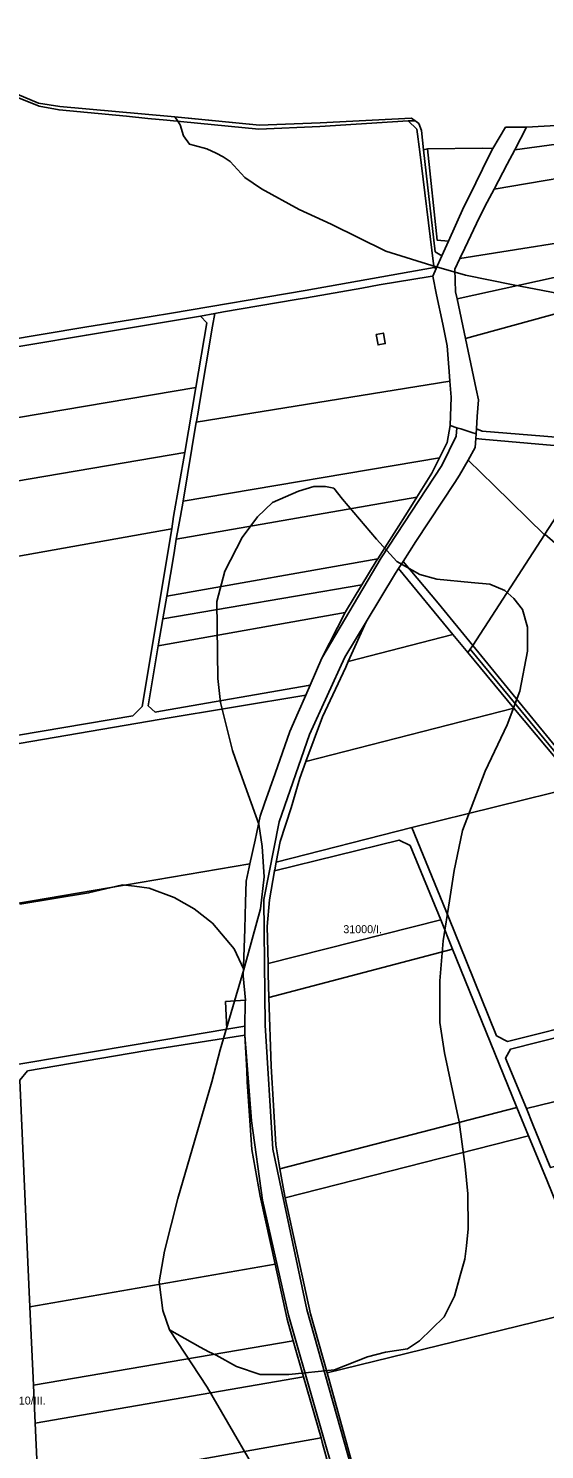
# Model space of a CAD drawing. Extents: x -541351 to -537540, y -1162694 to -1159725.
# Drawn here: x -539786 to -539463, y -1160828 to -1159940 of the extents above; entities that cross this region are included whole.
import ezdxf

# ---------------------------------------------------------------- set-up
doc = ezdxf.new("R2010")
doc.units = 0
for name, color, linetype in [('95560013', 7, 'Continuous'), ('95600013', 7, 'Continuous'), ('95610013', 7, 'Continuous'), ('95640013', 7, 'Continuous'), ('95660013', 7, 'Continuous')]:
    doc.layers.add(name, color=color, linetype=linetype)

msp = doc.modelspace()

# ---------------------------------------------------------------- linework, layer by layer
at = {"layer": '95560013'}
for points in [[(-539308.49, -1159974.08), (-539354.55, -1159990.5), (-539425.35, -1160007.86), (-539482.04, -1160015.57), (-539474.65, -1160001.49), (-539441.58, -1159999.6), (-539426.66, -1159997.49), (-539378.27, -1159985.56), (-539357.29, -1159979.97), (-539338.63, -1159973.85), (-539312.29, -1159964.05), (-539277.38, -1159950.13), (-539253.79, -1159939.77), (-539256.52, -1159952.89)], [(-539482.04, -1160015.57), (-539425.35, -1160007.86), (-539354.55, -1159990.5), (-539308.49, -1159974.08), (-539256.52, -1159952.89), (-539261.76, -1159978), (-539348.12, -1160009.46), (-539421.4, -1160027.65), (-539494.95, -1160040.2), (-539486.82, -1160024.7)], [(-539261.76, -1159978), (-539266.2, -1159999.29), (-539267.32, -1160019.26), (-539320.05, -1160041.46), (-539357.51, -1160053.36), (-539416.53, -1160067.73), (-539516.34, -1160083.61), (-539513.23, -1160077.01), (-539504.15, -1160057.74), (-539499.27, -1160048.44), (-539494.95, -1160040.2), (-539421.4, -1160027.65), (-539348.12, -1160009.46)], [(-539502.2, -1160014.56), (-539495.67, -1160014.74), (-539497.71, -1160018.84), (-539510.76, -1160045.13), (-539513.78, -1160051.22), (-539523.43, -1160072.73), (-539530.43, -1160072.14), (-539536.54, -1160014.93)], [(-539516.34, -1160083.61), (-539416.53, -1160067.73), (-539357.51, -1160053.36), (-539320.05, -1160041.46), (-539267.32, -1160019.26), (-539267.84, -1160031.16), (-539267.74, -1160037), (-539315.38, -1160054.86), (-539352.56, -1160067.89), (-539407.25, -1160084.31), (-539518.09, -1160108.82), (-539519.03, -1160104.35), (-539519.41, -1160090.12)], [(-539347.53, -1160084.05), (-539398.26, -1160102.11), (-539512.88, -1160133.53), (-539518.09, -1160108.82), (-539407.25, -1160084.31), (-539352.56, -1160067.89), (-539315.38, -1160054.86), (-539267.74, -1160037), (-539267.44, -1160054.36)], [(-539512.88, -1160133.53), (-539398.26, -1160102.11), (-539347.53, -1160084.05), (-539267.44, -1160054.36), (-539250.94, -1160160.23), (-539385.29, -1160241.92), (-539422.88, -1160197.87), (-539502.48, -1160191.42), (-539505.96, -1160190.04), (-539505.45, -1160182.31), (-539504.78, -1160171.93), (-539506.16, -1160165.16)], [(-539861.7, -1160150.32), (-539749.73, -1160131.42), (-539678.3, -1160119.6), (-539674.35, -1160123.79), (-539681.25, -1160164.2), (-539874.79, -1160196.79), (-539867.81, -1160155.49)], [(-539521.72, -1160170.16), (-539522.29, -1160187.99), (-539524.21, -1160198.49), (-539528.99, -1160208.07), (-539689.24, -1160235.28), (-539681.12, -1160185.89), (-539522.63, -1160160.16)], [(-539874.79, -1160196.79), (-539681.25, -1160164.2), (-539688.29, -1160204.74), (-539881.63, -1160237.63)], [(-539463.53, -1160256.34), (-539494.99, -1160225.44), (-539511.16, -1160209.5), (-539506.72, -1160201.77), (-539506.35, -1160196.13), (-539502.7, -1160196.39), (-539428.87, -1160202.88), (-539463.26, -1160255.92)], [(-539695.22, -1160244.7), (-539696.27, -1160252.43), (-539890.14, -1160287.05), (-539882.34, -1160242.43), (-539881.63, -1160237.63), (-539688.29, -1160204.74)], [(-539528.99, -1160208.07), (-539533.82, -1160217.78), (-539543.16, -1160232.76), (-539693.55, -1160258.99), (-539690.99, -1160244.62), (-539689.24, -1160235.28)], [(-539548.99, -1160242.09), (-539555.83, -1160252.97), (-539567.65, -1160271.23), (-539699.48, -1160294.6), (-539694.9, -1160267.58), (-539693.55, -1160258.99), (-539543.16, -1160232.76)], [(-539905.29, -1160399.99), (-539909.12, -1160395.76), (-539896.76, -1160325.74), (-539890.14, -1160287.05), (-539696.27, -1160252.43), (-539714.91, -1160363.54), (-539720.67, -1160369.29), (-539807.19, -1160383.95)], [(-539567.65, -1160271.23), (-539568.53, -1160272.74), (-539577.57, -1160287.59), (-539701.9, -1160308.8), (-539699.48, -1160294.6)], [(-539586.08, -1160335.4), (-539574.91, -1160310.55), (-539556.49, -1160280.21), (-539554.76, -1160277.35), (-539520.69, -1160318.51)], [(-539587.98, -1160304.74), (-539704.76, -1160325.55), (-539701.9, -1160308.8), (-539577.57, -1160287.59), (-539587.82, -1160304.43)], [(-539711.05, -1160363.13), (-539704.76, -1160325.55), (-539587.98, -1160304.74), (-539602.6, -1160333.33), (-539609.97, -1160350.24), (-539703.31, -1160366.41), (-539706.71, -1160366.98)], [(-539602.14, -1160370.05), (-539587.64, -1160338.97), (-539586.08, -1160335.4), (-539520.69, -1160318.51), (-539511.37, -1160329.79), (-539482.59, -1160364.66), (-539612.5, -1160397.88)], [(-539622.59, -1160379.21), (-539631.8, -1160405.4), (-539638.38, -1160424.12), (-539641.15, -1160432), (-539644.34, -1160446.97), (-539647.54, -1160461.93), (-539784.61, -1160485.12), (-539921.72, -1160508.25), (-539926.62, -1160497.29), (-539911.84, -1160410.99), (-539905.99, -1160405.21), (-539806.59, -1160389.16), (-539702.88, -1160371.48), (-539612.64, -1160356.38), (-539617.44, -1160367.38)], [(-539441.86, -1160413.3), (-539546.4, -1160439.25), (-539631.19, -1160460.88), (-539628.67, -1160447.82), (-539621.83, -1160426.91), (-539616.32, -1160408.3), (-539612.5, -1160397.88), (-539482.59, -1160364.66)], [(-539546.4, -1160439.25), (-539441.86, -1160413.3), (-539435.54, -1160421.37), (-539418.31, -1160436.62), (-539347.78, -1160481.25), (-539330.09, -1160492.45), (-539328.62, -1160499.34), (-539351.71, -1160533.5), (-539356, -1160539.85), (-539433.55, -1160559.47), (-539486.63, -1160572.87), (-539493.35, -1160569.31), (-539512.18, -1160522.86), (-539523.19, -1160495.68)], [(-539636.18, -1160524.12), (-539636.65, -1160500.97), (-539635.21, -1160484.43), (-539632.14, -1160466.29), (-539554.27, -1160447.02), (-539547.47, -1160450.3), (-539528.32, -1160496.8)], [(-539650.35, -1160547.02), (-539662.68, -1160547.97), (-539661.99, -1160565.14), (-539713.66, -1160573.83), (-539798.17, -1160588.09), (-539919.97, -1160607.67), (-539919.25, -1160512.88), (-539921.72, -1160508.25), (-539784.61, -1160485.12), (-539647.54, -1160461.93), (-539647.95, -1160463.89), (-539649.83, -1160472.69), (-539650.25, -1160485.84), (-539650.77, -1160502.39), (-539651.71, -1160531.92)], [(-539636.18, -1160530.77), (-539636.18, -1160524.12), (-539528.32, -1160496.8), (-539520.92, -1160515.12), (-539635.66, -1160545.36)], [(-539635.66, -1160545.36), (-539520.92, -1160515.12), (-539494.62, -1160579.82), (-539480.65, -1160614.14), (-539628.8, -1160652.38), (-539631.37, -1160637.5), (-539634.2, -1160588.33)], [(-539661.99, -1160565.14), (-539662.68, -1160547.97), (-539650.35, -1160547.02), (-539650.41, -1160548.28), (-539650.6, -1160563.3)], [(-539474.71, -1160614.69), (-539487.77, -1160583.34), (-539484.64, -1160577.59), (-539432.01, -1160564.25), (-539361.14, -1160546.51), (-539353.04, -1160549.08), (-539330.05, -1160579.53)], [(-539646.24, -1160640.35), (-539641.09, -1160669.51), (-539631.78, -1160712.13), (-539785.07, -1160738.8), (-539786.27, -1160710.83), (-539791.3, -1160596.99), (-539786.42, -1160591.13), (-539713.08, -1160578.81), (-539650.68, -1160568.9), (-539649.42, -1160590.92), (-539649.14, -1160598.17)], [(-539307.63, -1160614.15), (-539459.78, -1160651.69), (-539460.16, -1160650.71), (-539470.7, -1160624.83), (-539474.71, -1160614.69), (-539330.05, -1160579.53), (-539328.91, -1160581.29), (-539323.61, -1160589.17)], [(-539625.46, -1160670.68), (-539626.36, -1160666.27), (-539628.8, -1160652.38), (-539480.65, -1160614.14), (-539473.34, -1160631.89)], [(-539599.23, -1160779.87), (-539609.66, -1160743.12), (-539625.46, -1160670.68), (-539473.34, -1160631.89), (-539461.68, -1160659.92), (-539430.38, -1160737.54), (-539429.99, -1160738.47)], [(-539631.78, -1160712.13), (-539624.15, -1160746.4), (-539620.46, -1160759.86), (-539782.71, -1160787.7), (-539785.07, -1160738.8)], [(-539571.49, -1160879.49), (-539576.96, -1160860.94), (-539589.32, -1160816.2), (-539599.23, -1160779.87), (-539429.99, -1160738.47), (-539398.34, -1160816), (-539391.52, -1160833.04)], [(-539613.99, -1160782.56), (-539781.7, -1160811.46), (-539782.12, -1160801.98), (-539782.71, -1160787.7), (-539620.46, -1160759.86)], [(-539779.88, -1160852.13), (-539781.7, -1160811.46), (-539613.99, -1160782.56), (-539603.06, -1160820.51)], [(-539779.88, -1160852.13), (-539603.06, -1160820.51), (-539602.29, -1160823.36), (-539590.37, -1160867.23), (-539585.53, -1160883.06), (-539772.26, -1160915.27), (-539777.27, -1160910.84)]]:
    msp.add_lwpolyline(points, close=True, dxfattribs=at)
for points in [[(-539807.19, -1160383.95), (-539720.67, -1160369.29), (-539714.91, -1160363.54), (-539696.27, -1160252.43), (-539695.22, -1160244.7), (-539688.29, -1160204.74), (-539681.25, -1160164.2), (-539674.35, -1160123.79), (-539678.3, -1160119.6), (-539669.5, -1160118.03), (-539670.89, -1160125.91), (-539678.95, -1160174.24), (-539679.95, -1160179.6), (-539680.94, -1160185.37), (-539681.12, -1160185.89), (-539689.24, -1160235.28), (-539690.99, -1160244.62), (-539693.55, -1160258.99), (-539694.9, -1160267.58), (-539699.48, -1160294.6), (-539701.9, -1160308.8), (-539704.76, -1160325.55), (-539711.05, -1160363.13), (-539706.71, -1160366.98), (-539703.31, -1160366.41), (-539609.97, -1160350.24), (-539612.64, -1160356.38), (-539702.88, -1160371.48), (-539806.59, -1160389.16)], [(-539428.87, -1160202.88), (-539502.7, -1160196.39), (-539506.35, -1160196.13), (-539506.17, -1160193.22), (-539505.96, -1160190.04), (-539502.48, -1160191.42), (-539422.88, -1160197.87)], [(-539461.68, -1160659.92), (-539473.34, -1160631.89), (-539480.65, -1160614.14), (-539494.62, -1160579.82), (-539520.92, -1160515.12), (-539528.32, -1160496.8), (-539547.47, -1160450.3), (-539554.27, -1160447.02), (-539632.14, -1160466.29), (-539632.01, -1160465.71), (-539631.19, -1160460.88), (-539546.4, -1160439.25), (-539523.19, -1160495.68), (-539512.18, -1160522.86), (-539493.35, -1160569.31), (-539486.63, -1160572.87), (-539433.55, -1160559.47)], [(-539432.01, -1160564.25), (-539484.64, -1160577.59), (-539487.77, -1160583.34), (-539474.71, -1160614.69), (-539470.7, -1160624.83), (-539460.16, -1160650.71)]]:
    msp.add_lwpolyline(points, dxfattribs=at)
at = {"layer": '95600013'}
for points in [[(-539681.12, -1160185.89), (-539680.94, -1160185.37), (-539679.95, -1160179.6), (-539678.95, -1160174.24), (-539670.89, -1160125.91), (-539669.5, -1160118.03), (-539664, -1160116.8), (-539618.67, -1160109.28), (-539612.07, -1160108.19), (-539577.54, -1160102), (-539566.81, -1160100.08), (-539534.95, -1160094.86), (-539533.26, -1160094.63), (-539530.85, -1160106.21), (-539527.02, -1160124.61), (-539524.2, -1160138.12), (-539523.4, -1160148.87), (-539523.04, -1160154.15), (-539522.63, -1160160.16)], [(-539567.41, -1160137.56), (-539562.94, -1160136.68), (-539564.1, -1160130.19), (-539568.58, -1160131.08)]]:
    msp.add_lwpolyline(points, close=True, dxfattribs=at)
at = {"layer": '95610013'}
for points in [[(-539463.53, -1160256.34), (-539508.32, -1160325.42), (-539529.95, -1160299.04), (-539551.86, -1160272.91), (-539543.76, -1160260.52), (-539519.57, -1160223.53), (-539516.64, -1160219.04), (-539511.16, -1160209.5), (-539494.99, -1160225.44)], [(-539338.32, -1160364.79), (-539393.71, -1160438.45), (-539395.56, -1160440.92), (-539397.21, -1160443.12), (-539416.61, -1160431.81), (-539432.78, -1160417.52), (-539479.17, -1160360.89), (-539508.32, -1160325.42), (-539463.53, -1160256.34), (-539463.26, -1160255.92)]]:
    msp.add_lwpolyline(points, close=True, dxfattribs=at)
at = {"layer": '95640013'}
for points in [[(-539798.34, -1159980.7), (-539779.23, -1159988.26), (-539766.75, -1159990.7), (-539724.64, -1159994.55), (-539711.31, -1159995.96), (-539699.4, -1159997.18), (-539641.86, -1160002.73), (-539603.82, -1160001.07), (-539558.33, -1159998.22), (-539548.59, -1159997.61), (-539543.22, -1160002.75), (-539541.38, -1160016.88), (-539532.72, -1160086.9), (-539532.31, -1160089.25), (-539613.04, -1160103.64), (-539696.46, -1160117.7), (-539709.27, -1160119.9), (-539750.65, -1160126.47), (-539852.54, -1160143.49)], [(-539796.96, -1159979.23), (-539779.53, -1159986.52), (-539766.36, -1159988.66), (-539696.71, -1159994.91), (-539641.55, -1160000.23), (-539603.54, -1159998.8), (-539558.79, -1159996.56), (-539546.53, -1159995.95), (-539544.3, -1159997.55), (-539548.59, -1159997.61), (-539558.33, -1159998.22), (-539603.82, -1160001.07), (-539641.86, -1160002.73), (-539699.4, -1159997.18), (-539711.31, -1159995.96), (-539724.64, -1159994.55), (-539766.75, -1159990.7), (-539779.23, -1159988.26), (-539798.34, -1159980.7)], [(-539590.55, -1160859.01), (-539623.5, -1160743.95), (-539639.73, -1160672.1), (-539646.54, -1160622.42), (-539650.68, -1160568.9), (-539650.6, -1160563.3), (-539650.41, -1160548.28), (-539650.35, -1160547.02), (-539651.71, -1160531.92), (-539650.77, -1160502.39), (-539650.25, -1160485.84), (-539649.83, -1160472.69), (-539647.95, -1160463.89), (-539647.54, -1160461.93), (-539644.34, -1160446.97), (-539641.15, -1160432), (-539638.38, -1160424.12), (-539631.8, -1160405.4), (-539622.59, -1160379.21), (-539617.44, -1160367.38), (-539612.64, -1160356.38), (-539609.97, -1160350.24), (-539602.6, -1160333.33), (-539565.42, -1160270.64), (-539527.56, -1160212.97), (-539518.65, -1160194.69), (-539518.26, -1160189.3), (-539515.77, -1160190.1), (-539508.91, -1160192.33), (-539506.17, -1160193.22), (-539506.35, -1160196.13), (-539506.72, -1160201.77), (-539511.16, -1160209.5), (-539516.64, -1160219.04), (-539519.57, -1160223.53), (-539543.76, -1160260.52), (-539551.86, -1160272.91), (-539554.76, -1160277.35), (-539556.49, -1160280.21), (-539574.91, -1160310.55), (-539588.3, -1160332.61), (-539610.26, -1160381), (-539629.2, -1160435.51), (-539638.78, -1160484.23), (-539638.04, -1160562.66), (-539633.14, -1160640.18), (-539611.99, -1160740.35), (-539579.46, -1160855.53)], [(-539579.46, -1160855.53), (-539611.99, -1160740.35), (-539633.14, -1160640.18), (-539638.04, -1160562.66), (-539638.78, -1160484.23), (-539629.2, -1160435.51), (-539610.26, -1160381), (-539588.3, -1160332.61), (-539574.91, -1160310.55), (-539586.08, -1160335.4), (-539587.64, -1160338.97), (-539602.14, -1160370.05), (-539612.5, -1160397.88), (-539616.32, -1160408.3), (-539621.83, -1160426.91), (-539628.67, -1160447.82), (-539631.19, -1160460.88), (-539632.01, -1160465.71), (-539632.14, -1160466.29), (-539635.21, -1160484.43), (-539636.65, -1160500.97), (-539636.18, -1160524.12), (-539636.18, -1160530.77), (-539635.66, -1160545.36), (-539634.2, -1160588.33), (-539631.37, -1160637.5), (-539628.8, -1160652.38), (-539626.36, -1160666.27), (-539625.46, -1160670.68), (-539609.66, -1160743.12), (-539599.23, -1160779.87), (-539589.32, -1160816.2), (-539576.96, -1160860.94)], [(-539441.86, -1160413.3), (-539482.59, -1160364.66), (-539511.37, -1160329.79), (-539509.85, -1160327.61), (-539481.11, -1160362.43), (-539434.58, -1160419.19)], [(-539434.58, -1160419.19), (-539481.11, -1160362.43), (-539509.85, -1160327.61), (-539508.32, -1160325.42), (-539479.17, -1160360.89), (-539432.78, -1160417.52)], [(-539798.17, -1160588.09), (-539713.66, -1160573.83), (-539661.99, -1160565.14), (-539650.6, -1160563.3), (-539650.68, -1160568.9), (-539713.08, -1160578.81), (-539786.42, -1160591.13)], [(-539590.37, -1160867.23), (-539602.29, -1160823.36), (-539603.06, -1160820.51), (-539613.99, -1160782.56), (-539620.46, -1160759.86), (-539624.15, -1160746.4), (-539631.78, -1160712.13), (-539641.09, -1160669.51), (-539646.24, -1160640.35), (-539649.14, -1160598.17), (-539649.42, -1160590.92), (-539650.68, -1160568.9), (-539646.54, -1160622.42), (-539639.73, -1160672.1), (-539623.5, -1160743.95), (-539590.55, -1160859.01)], [(-539786.27, -1160710.83), (-539785.07, -1160738.8), (-539782.71, -1160787.7), (-539782.12, -1160801.98), (-539781.7, -1160811.46), (-539779.88, -1160852.13)]]:
    msp.add_lwpolyline(points, dxfattribs=at)
for points in [[(-539531.75, -1160079.29), (-539527.57, -1160081.95), (-539531.13, -1160089.89), (-539532.31, -1160089.25), (-539532.72, -1160086.9), (-539541.38, -1160016.88), (-539543.22, -1160002.75), (-539548.59, -1159997.61), (-539544.3, -1159997.55), (-539543.63, -1159998.03), (-539542.04, -1159999.17), (-539540.24, -1160003.61), (-539539, -1160015.66)], [(-539474.65, -1160001.49), (-539482.04, -1160015.57), (-539486.82, -1160024.7), (-539494.95, -1160040.2), (-539499.27, -1160048.44), (-539504.15, -1160057.74), (-539513.23, -1160077.01), (-539516.34, -1160083.61), (-539519.41, -1160090.12), (-539519.03, -1160104.35), (-539518.09, -1160108.82), (-539512.88, -1160133.53), (-539506.16, -1160165.16), (-539504.78, -1160171.93), (-539505.45, -1160182.31), (-539505.96, -1160190.04), (-539506.17, -1160193.22), (-539508.91, -1160192.33), (-539515.77, -1160190.1), (-539518.26, -1160189.3), (-539522.29, -1160187.99), (-539521.72, -1160170.16), (-539522.63, -1160160.16), (-539523.04, -1160154.15), (-539523.4, -1160148.87), (-539524.2, -1160138.12), (-539527.02, -1160124.61), (-539530.85, -1160106.21), (-539533.26, -1160094.63), (-539531.13, -1160089.89), (-539527.57, -1160081.95), (-539523.43, -1160072.73), (-539513.78, -1160051.22), (-539510.76, -1160045.13), (-539497.71, -1160018.84), (-539495.67, -1160014.74), (-539487.8, -1160001.56), (-539484.32, -1160001.54), (-539477.03, -1160001.5)], [(-539539, -1160015.66), (-539536.54, -1160014.93), (-539530.43, -1160072.14), (-539523.43, -1160072.73), (-539527.57, -1160081.95), (-539531.75, -1160079.29)], [(-539864.98, -1160141.1), (-539861.77, -1160144.89), (-539852.54, -1160143.49), (-539750.65, -1160126.47), (-539709.27, -1160119.9), (-539696.46, -1160117.7), (-539613.04, -1160103.64), (-539532.31, -1160089.25), (-539531.13, -1160089.89), (-539533.26, -1160094.63), (-539534.95, -1160094.86), (-539566.81, -1160100.08), (-539577.54, -1160102), (-539612.07, -1160108.19), (-539618.67, -1160109.28), (-539664, -1160116.8), (-539669.5, -1160118.03), (-539678.3, -1160119.6), (-539749.73, -1160131.42), (-539861.7, -1160150.32), (-539867.81, -1160155.49), (-539867.03, -1160150.82), (-539865.94, -1160143.31)], [(-539564.1, -1160130.19), (-539562.94, -1160136.68), (-539567.41, -1160137.56), (-539568.58, -1160131.08)], [(-539518.65, -1160194.69), (-539527.56, -1160212.97), (-539565.42, -1160270.64), (-539602.6, -1160333.33), (-539587.98, -1160304.74), (-539587.82, -1160304.43), (-539577.57, -1160287.59), (-539568.53, -1160272.74), (-539567.65, -1160271.23), (-539555.83, -1160252.97), (-539548.99, -1160242.09), (-539543.16, -1160232.76), (-539533.82, -1160217.78), (-539528.99, -1160208.07), (-539524.21, -1160198.49), (-539522.29, -1160187.99), (-539518.26, -1160189.3)], [(-539551.86, -1160272.91), (-539529.95, -1160299.04), (-539508.32, -1160325.42), (-539509.85, -1160327.61), (-539511.37, -1160329.79), (-539520.69, -1160318.51), (-539554.76, -1160277.35)]]:
    msp.add_lwpolyline(points, close=True, dxfattribs=at)
at = {"layer": '95660013'}
for points in [[(-539796.96, -1159979.23), (-539779.53, -1159986.52), (-539766.36, -1159988.66), (-539696.71, -1159994.91), (-539694.52, -1159995.12), (-539692.65, -1159997.83), (-539691.16, -1160000), (-539689.12, -1160007), (-539685.31, -1160012), (-539682.12, -1160013), (-539674.37, -1160015), (-539668.71, -1160017.78), (-539664.19, -1160020), (-539659.81, -1160023), (-539650.62, -1160033), (-539640.31, -1160040), (-539616.81, -1160053), (-539596.81, -1160062), (-539562.62, -1160079), (-539533.87, -1160088), (-539512.81, -1160094), (-539483, -1160100), (-539445.87, -1160107)], [(-539445.87, -1160107), (-539483, -1160100), (-539512.81, -1160094), (-539533.87, -1160088), (-539562.62, -1160079), (-539596.81, -1160062), (-539616.81, -1160053), (-539640.31, -1160040), (-539650.62, -1160033), (-539659.81, -1160023), (-539664.19, -1160020), (-539668.71, -1160017.78), (-539674.37, -1160015), (-539682.12, -1160013), (-539685.31, -1160012), (-539689.12, -1160007), (-539691.16, -1160000), (-539692.65, -1159997.83), (-539694.52, -1159995.12), (-539641.55, -1160000.23), (-539603.54, -1159998.8), (-539558.79, -1159996.56), (-539546.53, -1159995.95), (-539544.3, -1159997.55), (-539543.63, -1159998.03), (-539542.04, -1159999.17), (-539540.24, -1160003.61), (-539539, -1160015.66), (-539536.54, -1160014.93), (-539502.2, -1160014.56), (-539495.67, -1160014.74), (-539487.8, -1160001.56), (-539484.32, -1160001.54), (-539477.03, -1160001.5), (-539474.65, -1160001.49), (-539441.58, -1159999.6)], [(-539632.31, -1160861), (-539674.31, -1160789), (-539697.81, -1160753), (-539678.62, -1160764), (-539673.1, -1160766.78), (-539668.69, -1160769), (-539655.81, -1160776), (-539641.19, -1160781), (-539623.12, -1160781), (-539594.69, -1160778), (-539574.12, -1160770), (-539562.87, -1160767), (-539549.12, -1160765), (-539541.62, -1160760), (-539526.12, -1160745), (-539519.62, -1160732), (-539516.05, -1160719.22), (-539513.19, -1160709), (-539512.27, -1160700.56), (-539511.12, -1160690), (-539511.31, -1160668), (-539513, -1160651), (-539516.81, -1160623), (-539525.87, -1160580), (-539528.87, -1160561), (-539528.87, -1160535), (-539526.81, -1160510), (-539522.87, -1160485), (-539519.87, -1160466), (-539516.99, -1160452.11), (-539514.69, -1160441), (-539500.5, -1160404), (-539486.87, -1160375), (-539478.81, -1160354), (-539474.12, -1160329), (-539474.12, -1160314), (-539477.12, -1160303), (-539482.62, -1160296), (-539488.31, -1160291), (-539497.69, -1160287), (-539509.31, -1160286), (-539530.62, -1160284), (-539541.37, -1160281), (-539555.62, -1160273), (-539568.37, -1160259), (-539589.62, -1160234), (-539595.12, -1160227), (-539600.31, -1160226), (-539607.62, -1160226), (-539617.12, -1160229), (-539633.37, -1160236), (-539642.87, -1160245), (-539652.37, -1160258), (-539663.12, -1160279), (-539668.12, -1160298), (-539667.62, -1160346), (-539665.87, -1160361), (-539658.37, -1160391), (-539655.37, -1160400), (-539642, -1160437), (-539639.87, -1160451), (-539638.62, -1160470), (-539640.87, -1160490), (-539651.31, -1160528), (-539657.31, -1160515), (-539670.81, -1160499), (-539682.37, -1160490), (-539694.87, -1160483), (-539710.37, -1160477), (-539719.71, -1160475.89), (-539727.19, -1160475), (-539748.31, -1160480), (-539791.31, -1160487)], [(-539791.31, -1160487), (-539748.31, -1160480), (-539727.19, -1160475), (-539719.71, -1160475.89), (-539710.37, -1160477), (-539694.87, -1160483), (-539682.37, -1160490), (-539670.81, -1160499), (-539657.31, -1160515), (-539651.31, -1160528), (-539666.12, -1160578), (-539671.31, -1160598), (-539692.62, -1160671), (-539700.81, -1160704), (-539704.19, -1160723), (-539702, -1160741), (-539697.81, -1160753), (-539674.31, -1160789), (-539632.31, -1160861)]]:
    msp.add_lwpolyline(points, dxfattribs=at)
msp.add_lwpolyline([(-539697.81, -1160753), (-539702, -1160741), (-539704.19, -1160723), (-539700.81, -1160704), (-539692.62, -1160671), (-539671.31, -1160598), (-539666.12, -1160578), (-539651.31, -1160528), (-539640.87, -1160490), (-539638.62, -1160470), (-539639.87, -1160451), (-539642, -1160437), (-539655.37, -1160400), (-539658.37, -1160391), (-539665.87, -1160361), (-539667.62, -1160346), (-539668.12, -1160298), (-539663.12, -1160279), (-539652.37, -1160258), (-539642.87, -1160245), (-539633.37, -1160236), (-539617.12, -1160229), (-539607.62, -1160226), (-539600.31, -1160226), (-539595.12, -1160227), (-539589.62, -1160234), (-539568.37, -1160259), (-539555.62, -1160273), (-539541.37, -1160281), (-539530.62, -1160284), (-539509.31, -1160286), (-539497.69, -1160287), (-539488.31, -1160291), (-539482.62, -1160296), (-539477.12, -1160303), (-539474.12, -1160314), (-539474.12, -1160329), (-539478.81, -1160354), (-539486.87, -1160375), (-539500.5, -1160404), (-539514.69, -1160441), (-539516.99, -1160452.11), (-539519.87, -1160466), (-539522.87, -1160485), (-539526.81, -1160510), (-539528.87, -1160535), (-539528.87, -1160561), (-539525.87, -1160580), (-539516.81, -1160623), (-539513, -1160651), (-539511.31, -1160668), (-539511.12, -1160690), (-539512.27, -1160700.56), (-539513.19, -1160709), (-539516.05, -1160719.22), (-539519.62, -1160732), (-539526.12, -1160745), (-539541.62, -1160760), (-539549.12, -1160765), (-539562.87, -1160767), (-539574.12, -1160770), (-539594.69, -1160778), (-539623.12, -1160781), (-539641.19, -1160781), (-539655.81, -1160776), (-539668.69, -1160769), (-539673.1, -1160766.78), (-539678.62, -1160764)], close=True, dxfattribs=at)

# ---------------------------------------------------------------- texts
for s, rotation, p in [('31000/I.', 360, (-539589.15, -1160505.2)), ('31410/III.', 0, (-539803.09, -1160799.79))]:
    msp.add_text(s, height=5, rotation=rotation, dxfattribs=at).set_placement(p)

doc.saveas('drawing.dxf')
